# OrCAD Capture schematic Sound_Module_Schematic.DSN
size A; title: Sound_module
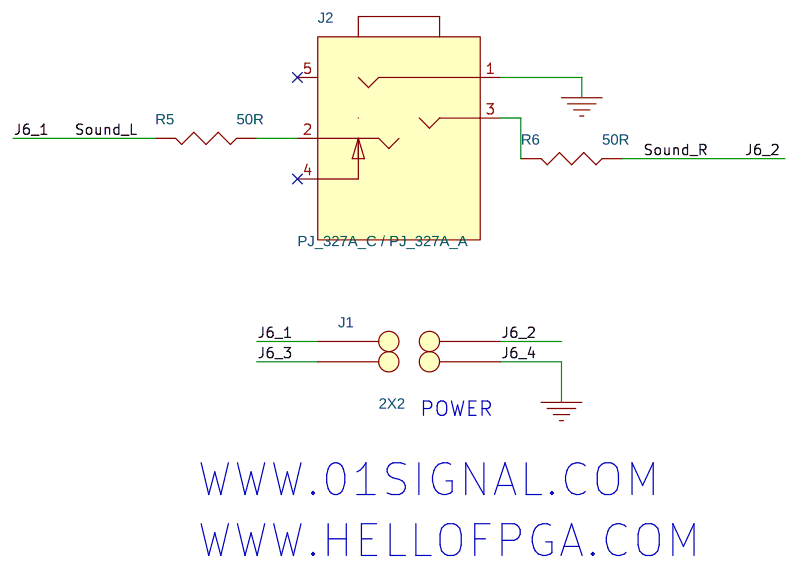
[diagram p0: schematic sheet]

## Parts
J1  2X2  [ISP2X2]
J2  PJ_327A_C / PJ_327A_A  [PJ_327A]
R5  50R  [R0603_1]
R6  50R  [R0603_1]

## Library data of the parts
J1 = CON_JACK_31
J2 = 1117S_18.3V
R5 R6 = R

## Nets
GND: J1.3 J2.1
J6_1: J1.1 R5.2
J6_2: J1.4 R6.1
J6_3: J1.2
N17507240: J2.3 R6.2
N17507248: J2.2 R5.1

Not connected (* = marked no-connect by the designer): J2 4* 5*

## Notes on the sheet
- POWER
- WWW.01SIGNAL.COM
- WWW.HELLOFPGA.COM
